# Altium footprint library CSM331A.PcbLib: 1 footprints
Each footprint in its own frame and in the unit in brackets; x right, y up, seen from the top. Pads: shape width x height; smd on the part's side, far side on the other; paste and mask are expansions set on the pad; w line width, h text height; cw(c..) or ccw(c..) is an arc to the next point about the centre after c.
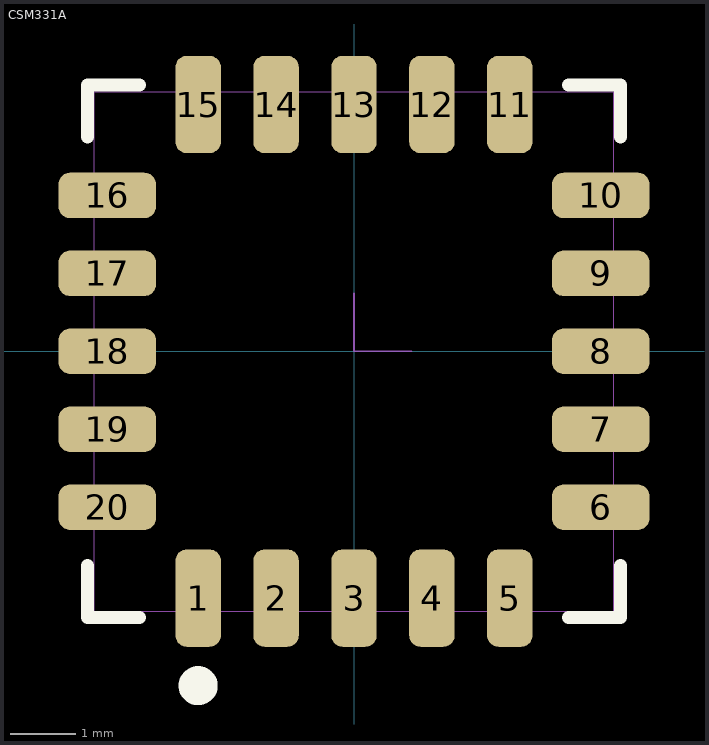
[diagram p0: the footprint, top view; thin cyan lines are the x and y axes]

## CSM331A [mm]
height 1
pads (20):
  rrect50% 0.7x1.5 smd mask+0.102: 1(-2.4,-3.8) 2(-1.2,-3.8) 3(0,-3.8) 4(1.2,-3.8) 5(2.4,-3.8) 11(2.4,3.8) 12(1.2,3.8) 13(0,3.8) 14(-1.2,3.8) 15(-2.4,3.8)
  rrect50% 1.5x0.7 smd mask+0.102: 6(3.8,-2.4) 7(3.8,-1.2) 8(3.8,0) 9(3.8,1.2) 10(3.8,2.4) 16(-3.8,2.4) 17(-3.8,1.2) 18(-3.8,0) 19(-3.8,-1.2) 20(-3.8,-2.4)
Top Overlay:
  circle w0.4: c-2.4,-5.149 r0.1
  circle w0.4: c-2.4,-5.149 r0.1
  circle w0.4: c-2.4,-5.149 r0.1
  lines w0.2: -4.1,-3.3 -4.1,-4.1 -3.3,-4.1 ; -4.1,3.3 -4.1,4.1 -3.3,4.1 ; 3.3,-4.1 4.1,-4.1 4.1,-3.3 ; 3.3,4.1 4.1,4.1 4.1,3.3
Mechanical 13:
  lines w0.013: -4,-4 -4,4 4,4 4,-4 -4,-4
Mechanical 15:
  lines w0.025: 0,0.889 0,0 0.889,0
3D body: height 3, standoff 0, extent -4,-4 4,4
